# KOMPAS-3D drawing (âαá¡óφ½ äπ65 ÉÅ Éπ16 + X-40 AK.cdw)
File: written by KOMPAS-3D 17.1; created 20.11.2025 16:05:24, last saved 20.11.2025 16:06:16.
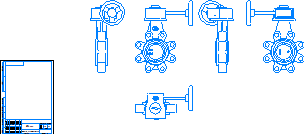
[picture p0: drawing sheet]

Sheet 1: A4, portrait

Title block, sheet 1: name: Сборка; material: Сталь 10  ГОСТ 1050-2013; mass: 7,62; sheets: 1; sheet format: A4

Views: Вид 1, Спереди, Проекционный вид 2, Проекционный вид 3, Проекционный вид 4, Проекционный вид 5
Referenced files in \\adlc.lan\data\АДЛ_ПКД\3D-модели\ADL production\Дисковые поворотные затворы ГРАНВЭЛ\с резьбовыми проушинами с китайским редуктором Ру 16\KOMPAS 3D\: Гранвэл Ду65 РП Ру16 + X-40 AK.m3d
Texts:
  Andrey
  АДЛ
Dimensions and other numbers on the sheet: 1:1; 1; 7,62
